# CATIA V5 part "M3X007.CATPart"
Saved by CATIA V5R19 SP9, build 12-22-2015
Part number: M3X007
Definition: design
Nomenclature: M3X007
Source: Unknown
Bounding box of the stored display mesh (mm): x -3.002 to 3.002, y -3.002 to 3.002, z 0 to 6
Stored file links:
  Z:\charly_robot\M3X007.CATPart
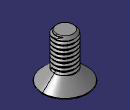
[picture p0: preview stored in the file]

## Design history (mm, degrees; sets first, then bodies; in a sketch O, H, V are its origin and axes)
AxisSystem1: origin (0, 0, 0), X (1, 0, 0), Y (0, 1, 0), Z (0, 0, 1)
Set1
  DatumSurface1 "OPEN_SHELL #267437"
Body1 (main body)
